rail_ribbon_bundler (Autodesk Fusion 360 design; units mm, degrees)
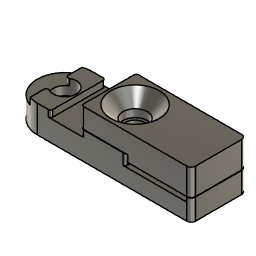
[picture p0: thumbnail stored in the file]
sketch "Sketch1" plane through (0, 0, 0) normal (0, 0, 1) x axis (1, 0, 0)
  line L1 (35, 6.25) -> (-6.25, 6.25)
  line L2 (-6.25, -6.25) -> (35, -6.25)
  line L3 (-6.25, 6.25) -> (-6.25, -6.25)
  line L4 (10, -6.25) -> (10, 6.25)
  line L5 (-2, -6.25) -> (-2, 6.25)
  line L6 (3, -6.25) -> (3, 6.25)
  line L7 (20, -6.25) -> (20, 6.25)
  line L8 (35, 6.25) -> (35, -6.25)
  line L9 (33.5, -6.25) -> (33.5, 6.25)
  line L10 (16, 0) -> (0, 0)
  circle C1 centre (0, 0) radius 2.625
  circle C2 centre (16, 0) radius 2.2
  circle C3 centre (16, 0) radius 2.75
  point P1 (0, 0)
  point P2 (0, 0)
  point P7 (10, 6.25)
  point P8 (10, -6.25)
  point P9 (-2, 6.25)
  point P10 (-2, -6.25)
  point P11 (3, 6.25)
  point P12 (3, -6.25)
  point P13 (20, 6.25)
  point P14 (20, -6.25)
  point P15 (33.5, 6.25)
  point P16 (33.5, -6.25)
  point P19 (0, 0)
  point P17 (16, 0)
  point P20 (16, 0)
  point P5 (35, -6.25)
  point P18 (16, 0)
  coincident P1 P2
  horizontal L1
  vertical L3
  coincident L1 P7
  coincident L2 P8
  perpendicular L2 L4
  coincident L1 P9
  coincident L2 P10
  perpendicular L2 L5
  coincident L1 P11
  coincident L2 P12
  perpendicular L2 L6
  horizontal L2
  coincident L1 P13
  coincident L2 P14
  perpendicular L2 L7
  vertical L8
  coincident L1 P15
  coincident L2 P16
  perpendicular L2 L9
  concentric C2 C3
  coincident P1 P19
  coincident P17 P20
  horizontal L10
  dimension "d1" diameter C1 = 5.25
  dimension "d2" distance P1 L3 = 6.25
  dimension "d3" distance P2 L1 = 6.25 (= "d2")
  dimension "d4" distance P1 L2 = 6.25 (= "d2")
  dimension "d5" distance P1 L4 = 10
  dimension "d6" distance P2 L6 = 3
  dimension "d7" distance P2 L5 = 2
  dimension "d46" distance P5 P16 = 1.5
  dimension "d47" distance L7 P16 = 13.5
  dimension "d48" diameter C2 = 4.4
  dimension "d49" diameter C3 = 5.5
  dimension "d50" distance P14 P18 = 4
  dimension "d51" distance P5 P8 = 25
extrude "Extrude1" new body sketch "Sketch1" profile of C1 L1 L2 L3 L4 L5 L6 L7 L8 L9 C2 C3 against normal blind 4.75 bodies "bundler-10p-bot"
extrude "Extrude2" add sketch "Sketch1" profile of C1 L1 L2 L4 L5 L6 L7 C2 C3 along normal blind 1.5
fillet "Fillet3" radius 0.5
chamfer "Chamfer1" distance 2.75
fillet "Fillet11" radius 6.25
extrude "Extrude5" cut sketch "Sketch1" profile of L1 L2 L7 L9 against normal blind 1
extrude "Extrude6" new body sketch "Sketch1" profile of L1 L2 L7 L8 L9 blind 6 from offset 0.1 bodies "bundler-10p-top"
extrude "Extrude7" sketch "Sketch1" profile of L1 L2 L4 L7 C3 to an object
combine "Combine1"
offset_faces "OffsetFaces1" distance -0.1
chamfer "Chamfer2" distance 2.75
fillet "Fillet13" radius 1
fillet "Fillet14" radius 0.5
fillet "Fillet15" radius 0.5
named bodies: "bundler-10p-bot", "bundler-10p-top"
